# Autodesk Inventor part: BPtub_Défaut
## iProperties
Shininess: 64.0
Length Units: 11269
Angle Units: 11279
Time Units: 11290
Mass Units: 11283
Length Display Precision: 3
Angle Display Precision: 2
Compacted: True
Part Number: BPtub_Défaut
Document SubType Name: Modeling
Created: 2006-11
Material: Par défaut
Designer: profs_sti
Density: 0.0
Volumn: 0.0
Area: 0.0
PropertySet Name: Model Information
Control State: 0
Master: False
Checked Out: False
Author: profs_sti
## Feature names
1. Base1
